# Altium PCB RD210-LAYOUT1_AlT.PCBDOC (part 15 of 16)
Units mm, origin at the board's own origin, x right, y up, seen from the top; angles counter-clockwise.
Board outline 330 x 300 mm, 6 copper layers (TOP, Mid-Layer 1, Mid-Layer 2, Mid-Layer 3, Mid-Layer 4, BOTTOM), stack 1.422 mm thick; 981 components, 463 nets, 2326 pads, 12534 vias.
Unrouted connection lines stored in the file: 6.
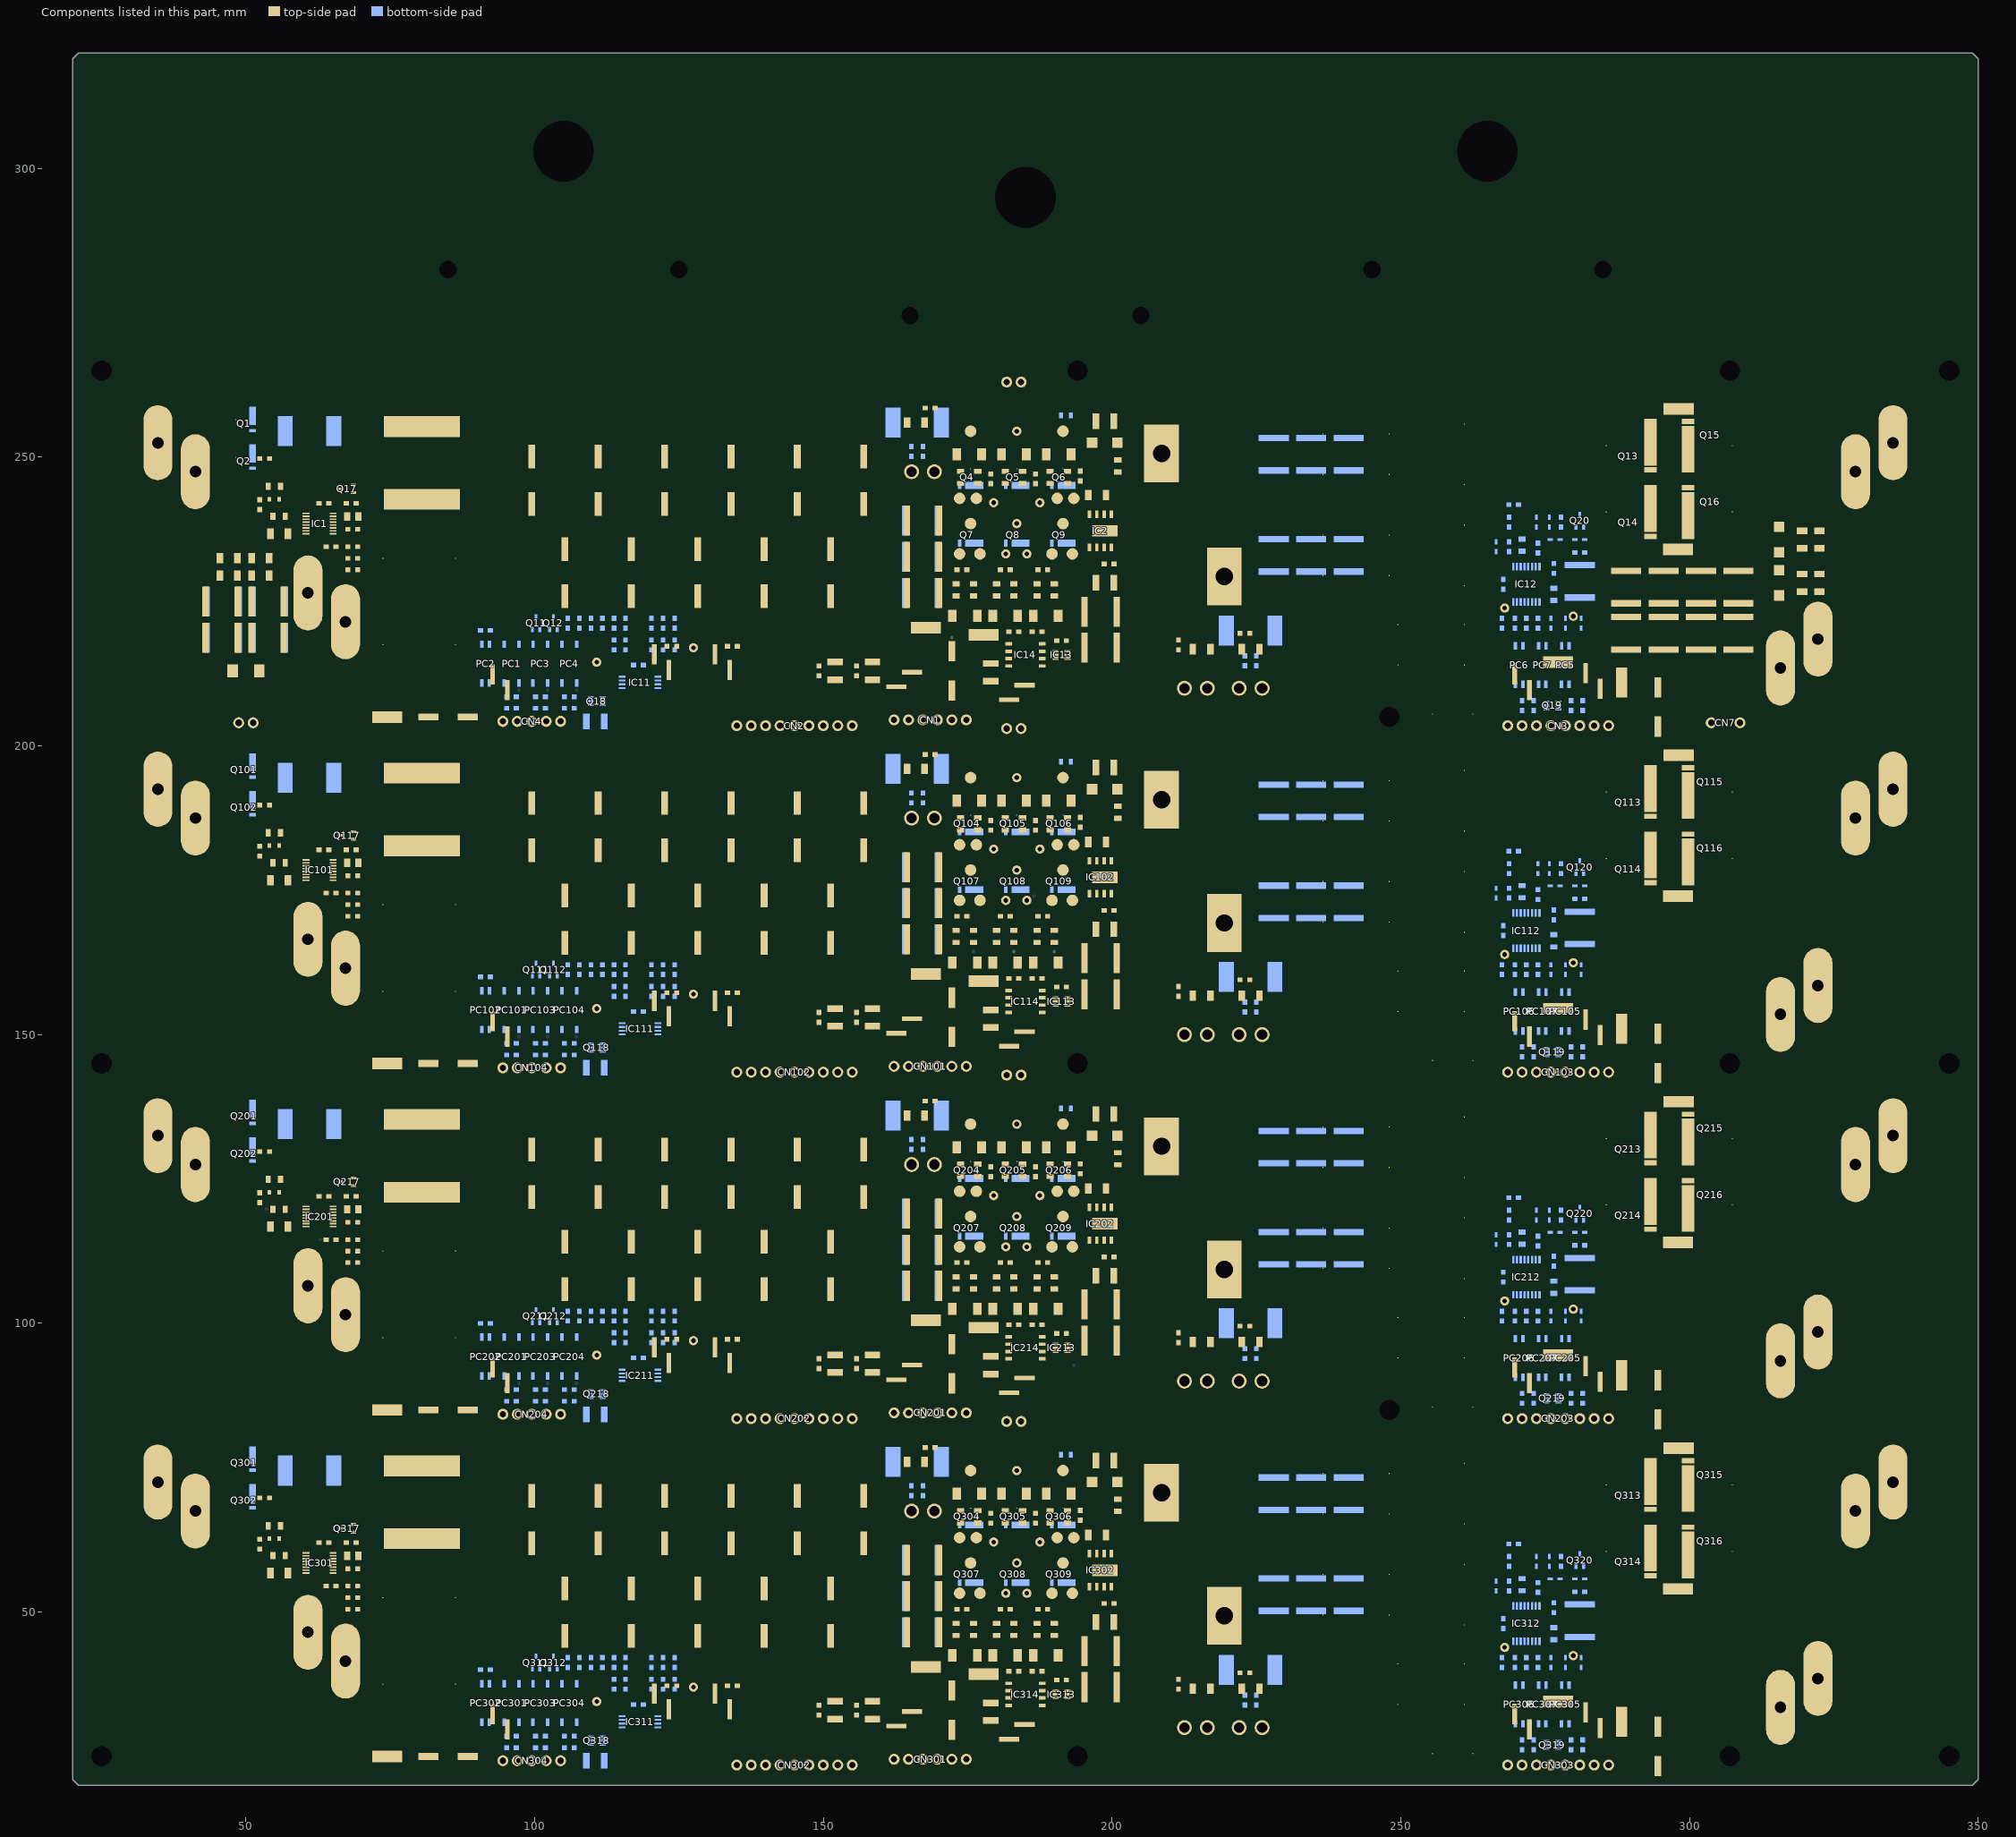
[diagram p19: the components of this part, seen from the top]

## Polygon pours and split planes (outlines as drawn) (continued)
no net on Bottom Paste "BOTTOMPASTE1205" (solid, pour order 0): 50.55,258.105 50.55,258.705 51.75,258.705 51.75,258.105
no net on Bottom Paste "BOTTOMPASTE1206" (solid, pour order 0): 44.75,254.295 44.75,254.895 45.95,254.895 45.95,254.295
no net on Bottom Paste "BOTTOMPASTE1207" (solid, pour order 0): 44.75,255.565 44.75,256.165 45.95,256.165 45.95,255.565
no net on Bottom Paste "BOTTOMPASTE1208" (solid, pour order 0): 44.75,256.835 44.75,257.435 45.95,257.435 45.95,256.835
no net on Bottom Paste "BOTTOMPASTE1209" (solid, pour order 0): 44.75,258.105 44.75,258.705 45.95,258.705 45.95,258.105
no net on Bottom Paste "BOTTOMPASTE1210" (solid, pour order 0): 48,256.7 48,258.355 49.2,258.355 49.2,256.7
no net on Bottom Paste "BOTTOMPASTE1211" (solid, pour order 0): 46.4,256.7 46.4,258.355 47.6,258.355 47.6,256.7
no net on Bottom Paste "BOTTOMPASTE1212" (solid, pour order 0): 46.4,254.645 46.4,256.3 47.6,256.3 47.6,254.645
no net on Bottom Paste "BOTTOMPASTE1213" (solid, pour order 0): 48,254.645 48,256.3 49.2,256.3 49.2,254.645
no net on Bottom Paste "BOTTOMPASTE1214" (solid, pour order 0): 50.55,249.065 50.55,249.665 51.75,249.665 51.75,249.065
no net on Bottom Paste "BOTTOMPASTE1215" (solid, pour order 0): 50.55,251.605 50.55,252.205 51.75,252.205 51.75,251.605
no net on Bottom Paste "BOTTOMPASTE1216" (solid, pour order 0): 44.75,247.795 44.75,248.395 45.95,248.395 45.95,247.795
no net on Bottom Paste "BOTTOMPASTE1217" (solid, pour order 0): 44.75,249.065 44.75,249.665 45.95,249.665 45.95,249.065
no net on Bottom Paste "BOTTOMPASTE1218" (solid, pour order 0): 44.75,250.335 44.75,250.935 45.95,250.935 45.95,250.335
no net on Bottom Paste "BOTTOMPASTE1219" (solid, pour order 0): 44.75,251.605 44.75,252.205 45.95,252.205 45.95,251.605
no net on Bottom Paste "BOTTOMPASTE1220" (solid, pour order 0): 48,250.2 48,251.855 49.2,251.855 49.2,250.2
no net on Bottom Paste "BOTTOMPASTE1221" (solid, pour order 0): 46.4,250.2 46.4,251.855 47.6,251.855 47.6,250.2
no net on Bottom Paste "BOTTOMPASTE1222" (solid, pour order 0): 46.4,248.145 46.4,249.8 47.6,249.8 47.6,248.145
no net on Bottom Paste "BOTTOMPASTE1223" (solid, pour order 0): 48,248.145 48,249.8 49.2,249.8 49.2,248.145
no net on Bottom Paste "BOTTOMPASTE1224" (solid, pour order 0): 50.55,195.565 50.55,196.165 51.75,196.165 51.75,195.565
no net on Bottom Paste "BOTTOMPASTE1225" (solid, pour order 0): 50.55,198.105 50.55,198.705 51.75,198.705 51.75,198.105
no net on Bottom Paste "BOTTOMPASTE1226" (solid, pour order 0): 44.75,194.295 44.75,194.895 45.95,194.895 45.95,194.295
no net on Bottom Paste "BOTTOMPASTE1227" (solid, pour order 0): 44.75,195.565 44.75,196.165 45.95,196.165 45.95,195.565
no net on Bottom Paste "BOTTOMPASTE1228" (solid, pour order 0): 44.75,196.835 44.75,197.435 45.95,197.435 45.95,196.835
no net on Bottom Paste "BOTTOMPASTE1229" (solid, pour order 0): 44.75,198.105 44.75,198.705 45.95,198.705 45.95,198.105
no net on Bottom Paste "BOTTOMPASTE1230" (solid, pour order 0): 48,196.7 48,198.355 49.2,198.355 49.2,196.7
no net on Bottom Paste "BOTTOMPASTE1231" (solid, pour order 0): 46.4,196.7 46.4,198.355 47.6,198.355 47.6,196.7
no net on Bottom Paste "BOTTOMPASTE1232" (solid, pour order 0): 46.4,194.645 46.4,196.3 47.6,196.3 47.6,194.645
no net on Bottom Paste "BOTTOMPASTE1233" (solid, pour order 0): 48,194.645 48,196.3 49.2,196.3 49.2,194.645
no net on Bottom Paste "BOTTOMPASTE1234" (solid, pour order 0): 50.55,189.065 50.55,189.665 51.75,189.665 51.75,189.065
no net on Bottom Paste "BOTTOMPASTE1235" (solid, pour order 0): 50.55,191.605 50.55,192.205 51.75,192.205 51.75,191.605
no net on Bottom Paste "BOTTOMPASTE1236" (solid, pour order 0): 44.75,187.795 44.75,188.395 45.95,188.395 45.95,187.795
no net on Bottom Paste "BOTTOMPASTE1237" (solid, pour order 0): 44.75,189.065 44.75,189.665 45.95,189.665 45.95,189.065
no net on Bottom Paste "BOTTOMPASTE1238" (solid, pour order 0): 44.75,190.335 44.75,190.935 45.95,190.935 45.95,190.335
no net on Bottom Paste "BOTTOMPASTE1239" (solid, pour order 0): 44.75,191.605 44.75,192.205 45.95,192.205 45.95,191.605
no net on Bottom Paste "BOTTOMPASTE1240" (solid, pour order 0): 48,190.2 48,191.855 49.2,191.855 49.2,190.2
no net on Bottom Paste "BOTTOMPASTE1241" (solid, pour order 0): 46.4,190.2 46.4,191.855 47.6,191.855 47.6,190.2
no net on Bottom Paste "BOTTOMPASTE1242" (solid, pour order 0): 46.4,188.145 46.4,189.8 47.6,189.8 47.6,188.145
no net on Bottom Paste "BOTTOMPASTE1243" (solid, pour order 0): 48,188.145 48,189.8 49.2,189.8 49.2,188.145
no net on Bottom Paste "BOTTOMPASTE1244" (solid, pour order 0): 174.565,184.5 174.565,185.7 175.165,185.7 175.165,184.5
no net on Bottom Paste "BOTTOMPASTE1245" (solid, pour order 0): 177.105,184.5 177.105,185.7 177.705,185.7 177.705,184.5
no net on Bottom Paste "BOTTOMPASTE1246" (solid, pour order 0): 173.295,190.3 173.295,191.5 173.895,191.5 173.895,190.3
no net on Bottom Paste "BOTTOMPASTE1247" (solid, pour order 0): 174.565,190.3 174.565,191.5 175.165,191.5 175.165,190.3
no net on Bottom Paste "BOTTOMPASTE1248" (solid, pour order 0): 175.835,190.3 175.835,191.5 176.435,191.5 176.435,190.3
no net on Bottom Paste "BOTTOMPASTE1249" (solid, pour order 0): 177.105,190.3 177.105,191.5 177.705,191.5 177.705,190.3
no net on Bottom Paste "BOTTOMPASTE1250" (solid, pour order 0): 175.7,187.05 175.7,188.25 177.355,188.25 177.355,187.05
no net on Bottom Paste "BOTTOMPASTE1251" (solid, pour order 0): 175.7,188.65 175.7,189.85 177.355,189.85 177.355,188.65
no net on Bottom Paste "BOTTOMPASTE1252" (solid, pour order 0): 173.645,188.65 173.645,189.85 175.3,189.85 175.3,188.65
no net on Bottom Paste "BOTTOMPASTE1253" (solid, pour order 0): 173.645,187.05 173.645,188.25 175.3,188.25 175.3,187.05
no net on Bottom Paste "BOTTOMPASTE1254" (solid, pour order 0): 182.565,184.5 182.565,185.7 183.165,185.7 183.165,184.5
no net on Bottom Paste "BOTTOMPASTE1255" (solid, pour order 0): 185.105,184.5 185.105,185.7 185.705,185.7 185.705,184.5
no net on Bottom Paste "BOTTOMPASTE1256" (solid, pour order 0): 181.295,190.3 181.295,191.5 181.895,191.5 181.895,190.3
no net on Bottom Paste "BOTTOMPASTE1257" (solid, pour order 0): 182.565,190.3 182.565,191.5 183.165,191.5 183.165,190.3
no net on Bottom Paste "BOTTOMPASTE1258" (solid, pour order 0): 183.835,190.3 183.835,191.5 184.435,191.5 184.435,190.3
no net on Bottom Paste "BOTTOMPASTE1259" (solid, pour order 0): 185.105,190.3 185.105,191.5 185.705,191.5 185.705,190.3
no net on Bottom Paste "BOTTOMPASTE1260" (solid, pour order 0): 183.7,187.05 183.7,188.25 185.355,188.25 185.355,187.05
no net on Bottom Paste "BOTTOMPASTE1261" (solid, pour order 0): 183.7,188.65 183.7,189.85 185.355,189.85 185.355,188.65
no net on Bottom Paste "BOTTOMPASTE1262" (solid, pour order 0): 181.645,188.65 181.645,189.85 183.3,189.85 183.3,188.65
no net on Bottom Paste "BOTTOMPASTE1263" (solid, pour order 0): 181.645,187.05 181.645,188.25 183.3,188.25 183.3,187.05
no net on Bottom Paste "BOTTOMPASTE1264" (solid, pour order 0): 190.565,184.5 190.565,185.7 191.165,185.7 191.165,184.5
no net on Bottom Paste "BOTTOMPASTE1265" (solid, pour order 0): 193.105,184.5 193.105,185.7 193.705,185.7 193.705,184.5
no net on Bottom Paste "BOTTOMPASTE1266" (solid, pour order 0): 189.295,190.3 189.295,191.5 189.895,191.5 189.895,190.3
no net on Bottom Paste "BOTTOMPASTE1267" (solid, pour order 0): 190.565,190.3 190.565,191.5 191.165,191.5 191.165,190.3
no net on Bottom Paste "BOTTOMPASTE1268" (solid, pour order 0): 191.835,190.3 191.835,191.5 192.435,191.5 192.435,190.3
no net on Bottom Paste "BOTTOMPASTE1269" (solid, pour order 0): 193.105,190.3 193.105,191.5 193.705,191.5 193.705,190.3
no net on Bottom Paste "BOTTOMPASTE1270" (solid, pour order 0): 191.7,187.05 191.7,188.25 193.355,188.25 193.355,187.05
no net on Bottom Paste "BOTTOMPASTE1271" (solid, pour order 0): 191.7,188.65 191.7,189.85 193.355,189.85 193.355,188.65
no net on Bottom Paste "BOTTOMPASTE1272" (solid, pour order 0): 189.645,188.65 189.645,189.85 191.3,189.85 191.3,188.65
no net on Bottom Paste "BOTTOMPASTE1273" (solid, pour order 0): 189.645,187.05 189.645,188.25 191.3,188.25 191.3,187.05
no net on Bottom Paste "BOTTOMPASTE1274" (solid, pour order 0): 174.565,174.5 174.565,175.7 175.165,175.7 175.165,174.5
no net on Bottom Paste "BOTTOMPASTE1275" (solid, pour order 0): 177.105,174.5 177.105,175.7 177.705,175.7 177.705,174.5
no net on Bottom Paste "BOTTOMPASTE1276" (solid, pour order 0): 173.295,180.3 173.295,181.5 173.895,181.5 173.895,180.3
no net on Bottom Paste "BOTTOMPASTE1277" (solid, pour order 0): 174.565,180.3 174.565,181.5 175.165,181.5 175.165,180.3
no net on Bottom Paste "BOTTOMPASTE1278" (solid, pour order 0): 175.835,180.3 175.835,181.5 176.435,181.5 176.435,180.3
no net on Bottom Paste "BOTTOMPASTE1279" (solid, pour order 0): 177.105,180.3 177.105,181.5 177.705,181.5 177.705,180.3
no net on Bottom Paste "BOTTOMPASTE1280" (solid, pour order 0): 175.7,177.05 175.7,178.25 177.355,178.25 177.355,177.05
no net on Bottom Paste "BOTTOMPASTE1281" (solid, pour order 0): 175.7,178.65 175.7,179.85 177.355,179.85 177.355,178.65
no net on Bottom Paste "BOTTOMPASTE1282" (solid, pour order 0): 173.645,178.65 173.645,179.85 175.3,179.85 175.3,178.65
no net on Bottom Paste "BOTTOMPASTE1283" (solid, pour order 0): 173.645,177.05 173.645,178.25 175.3,178.25 175.3,177.05
no net on Bottom Paste "BOTTOMPASTE1284" (solid, pour order 0): 182.565,174.5 182.565,175.7 183.165,175.7 183.165,174.5
no net on Bottom Paste "BOTTOMPASTE1285" (solid, pour order 0): 185.105,174.5 185.105,175.7 185.705,175.7 185.705,174.5
no net on Bottom Paste "BOTTOMPASTE1286" (solid, pour order 0): 181.295,180.3 181.295,181.5 181.895,181.5 181.895,180.3
no net on Bottom Paste "BOTTOMPASTE1287" (solid, pour order 0): 182.565,180.3 182.565,181.5 183.165,181.5 183.165,180.3
no net on Bottom Paste "BOTTOMPASTE1288" (solid, pour order 0): 183.835,180.3 183.835,181.5 184.435,181.5 184.435,180.3
no net on Bottom Paste "BOTTOMPASTE1289" (solid, pour order 0): 185.105,180.3 185.105,181.5 185.705,181.5 185.705,180.3
no net on Bottom Paste "BOTTOMPASTE1290" (solid, pour order 0): 183.7,177.05 183.7,178.25 185.355,178.25 185.355,177.05
no net on Bottom Paste "BOTTOMPASTE1291" (solid, pour order 0): 183.7,178.65 183.7,179.85 185.355,179.85 185.355,178.65
no net on Bottom Paste "BOTTOMPASTE1292" (solid, pour order 0): 181.645,178.65 181.645,179.85 183.3,179.85 183.3,178.65
no net on Bottom Paste "BOTTOMPASTE1293" (solid, pour order 0): 181.645,177.05 181.645,178.25 183.3,178.25 183.3,177.05
no net on Bottom Paste "BOTTOMPASTE1294" (solid, pour order 0): 190.565,174.5 190.565,175.7 191.165,175.7 191.165,174.5
no net on Bottom Paste "BOTTOMPASTE1295" (solid, pour order 0): 193.105,174.5 193.105,175.7 193.705,175.7 193.705,174.5
no net on Bottom Paste "BOTTOMPASTE1296" (solid, pour order 0): 189.295,180.3 189.295,181.5 189.895,181.5 189.895,180.3
no net on Bottom Paste "BOTTOMPASTE1297" (solid, pour order 0): 190.565,180.3 190.565,181.5 191.165,181.5 191.165,180.3
no net on Bottom Paste "BOTTOMPASTE1298" (solid, pour order 0): 191.835,180.3 191.835,181.5 192.435,181.5 192.435,180.3
no net on Bottom Paste "BOTTOMPASTE1299" (solid, pour order 0): 193.105,180.3 193.105,181.5 193.705,181.5 193.705,180.3
no net on Bottom Paste "BOTTOMPASTE1300" (solid, pour order 0): 191.7,177.05 191.7,178.25 193.355,178.25 193.355,177.05
no net on Bottom Paste "BOTTOMPASTE1301" (solid, pour order 0): 191.7,178.65 191.7,179.85 193.355,179.85 193.355,178.65
no net on Bottom Paste "BOTTOMPASTE1302" (solid, pour order 0): 189.645,178.65 189.645,179.85 191.3,179.85 191.3,178.65
no net on Bottom Paste "BOTTOMPASTE1303" (solid, pour order 0): 189.645,177.05 189.645,178.25 191.3,178.25 191.3,177.05
no net on Top Solder "TOPSOLDER1304" (solid, pour order 0): 292.1,248.5 292.1,249.5 294.4,249.5 294.4,248.5
no net on Top Solder "TOPSOLDER1305" (solid, pour order 0): 292.1,249.7 292.1,250.7 294.4,250.7 294.4,249.7
no net on Top Solder "TOPSOLDER1306" (solid, pour order 0): 292.1,250.9 292.1,251.9 294.4,251.9 294.4,250.9
no net on Top Solder "TOPSOLDER1307" (solid, pour order 0): 292.1,253.3 292.1,254.3 294.4,254.3 294.4,253.3
no net on Top Solder "TOPSOLDER1308" (solid, pour order 0): 292.1,254.5 292.1,255.5 294.4,255.5 294.4,254.5
no net on Top Solder "TOPSOLDER1309" (solid, pour order 0): 292.1,255.7 292.1,256.7 294.4,256.7 294.4,255.7
no net on Top Solder "TOPSOLDER1310" (solid, pour order 0): 292.1,237 292.1,238 294.4,238 294.4,237
no net on Top Solder "TOPSOLDER1311" (solid, pour order 0): 292.1,238.2 292.1,239.2 294.4,239.2 294.4,238.2
no net on Top Solder "TOPSOLDER1312" (solid, pour order 0): 292.1,239.4 292.1,240.4 294.4,240.4 294.4,239.4
no net on Top Solder "TOPSOLDER1313" (solid, pour order 0): 292.1,241.8 292.1,242.8 294.4,242.8 294.4,241.8
no net on Top Solder "TOPSOLDER1314" (solid, pour order 0): 292.1,243 292.1,244 294.4,244 294.4,243
no net on Top Solder "TOPSOLDER1315" (solid, pour order 0): 292.1,244.2 292.1,245.2 294.4,245.2 294.4,244.2
no net on Top Solder "TOPSOLDER1316" (solid, pour order 0): 298.6,254.5 298.6,255.5 300.9,255.5 300.9,254.5
no net on Top Solder "TOPSOLDER1317" (solid, pour order 0): 298.6,253.3 298.6,254.3 300.9,254.3 300.9,253.3
no net on Top Solder "TOPSOLDER1318" (solid, pour order 0): 298.6,252.1 298.6,253.1 300.9,253.1 300.9,252.1
no net on Top Solder "TOPSOLDER1319" (solid, pour order 0): 298.6,249.7 298.6,250.7 300.9,250.7 300.9,249.7
no net on Top Solder "TOPSOLDER1320" (solid, pour order 0): 298.6,248.5 298.6,249.5 300.9,249.5 300.9,248.5
no net on Top Solder "TOPSOLDER1321" (solid, pour order 0): 298.6,247.3 298.6,248.3 300.9,248.3 300.9,247.3
no net on Top Solder "TOPSOLDER1322" (solid, pour order 0): 298.6,243 298.6,244 300.9,244 300.9,243
no net on Top Solder "TOPSOLDER1323" (solid, pour order 0): 298.6,241.8 298.6,242.8 300.9,242.8 300.9,241.8
no net on Top Solder "TOPSOLDER1324" (solid, pour order 0): 298.6,240.6 298.6,241.6 300.9,241.6 300.9,240.6
no net on Top Solder "TOPSOLDER1325" (solid, pour order 0): 298.6,238.2 298.6,239.2 300.9,239.2 300.9,238.2
no net on Top Solder "TOPSOLDER1326" (solid, pour order 0): 298.6,237 298.6,238 300.9,238 300.9,237
no net on Top Solder "TOPSOLDER1327" (solid, pour order 0): 298.6,235.8 298.6,236.8 300.9,236.8 300.9,235.8
no net on Top Solder "TOPSOLDER1328" (solid, pour order 0): 292.1,177 292.1,178 294.4,178 294.4,177
no net on Top Solder "TOPSOLDER1329" (solid, pour order 0): 292.1,178.2 292.1,179.2 294.4,179.2 294.4,178.2
no net on Top Solder "TOPSOLDER1330" (solid, pour order 0): 292.1,179.4 292.1,180.4 294.4,180.4 294.4,179.4
no net on Top Solder "TOPSOLDER1331" (solid, pour order 0): 292.1,181.8 292.1,182.8 294.4,182.8 294.4,181.8
no net on Top Solder "TOPSOLDER1332" (solid, pour order 0): 292.1,183 292.1,184 294.4,184 294.4,183
no net on Top Solder "TOPSOLDER1333" (solid, pour order 0): 292.1,184.2 292.1,185.2 294.4,185.2 294.4,184.2
no net on Top Solder "TOPSOLDER1334" (solid, pour order 0): 292.1,188.5 292.1,189.5 294.4,189.5 294.4,188.5
no net on Top Solder "TOPSOLDER1335" (solid, pour order 0): 292.1,189.7 292.1,190.7 294.4,190.7 294.4,189.7
no net on Top Solder "TOPSOLDER1336" (solid, pour order 0): 292.1,190.9 292.1,191.9 294.4,191.9 294.4,190.9
no net on Top Solder "TOPSOLDER1337" (solid, pour order 0): 292.1,193.3 292.1,194.3 294.4,194.3 294.4,193.3
no net on Top Solder "TOPSOLDER1338" (solid, pour order 0): 292.1,194.5 292.1,195.5 294.4,195.5 294.4,194.5
no net on Top Solder "TOPSOLDER1339" (solid, pour order 0): 292.1,195.7 292.1,196.7 294.4,196.7 294.4,195.7
no net on Top Solder "TOPSOLDER1340" (solid, pour order 0): 298.6,183 298.6,184 300.9,184 300.9,183
no net on Top Solder "TOPSOLDER1341" (solid, pour order 0): 298.6,181.8 298.6,182.8 300.9,182.8 300.9,181.8
no net on Top Solder "TOPSOLDER1342" (solid, pour order 0): 298.6,180.6 298.6,181.6 300.9,181.6 300.9,180.6
no net on Top Solder "TOPSOLDER1343" (solid, pour order 0): 298.6,178.2 298.6,179.2 300.9,179.2 300.9,178.2
no net on Top Solder "TOPSOLDER1344" (solid, pour order 0): 298.6,177 298.6,178 300.9,178 300.9,177
no net on Top Solder "TOPSOLDER1345" (solid, pour order 0): 298.6,175.8 298.6,176.8 300.9,176.8 300.9,175.8
no net on Top Solder "TOPSOLDER1346" (solid, pour order 0): 298.6,194.5 298.6,195.5 300.9,195.5 300.9,194.5
no net on Top Solder "TOPSOLDER1347" (solid, pour order 0): 298.6,193.3 298.6,194.3 300.9,194.3 300.9,193.3
no net on Top Solder "TOPSOLDER1348" (solid, pour order 0): 298.6,192.1 298.6,193.1 300.9,193.1 300.9,192.1
no net on Top Solder "TOPSOLDER1349" (solid, pour order 0): 298.6,189.7 298.6,190.7 300.9,190.7 300.9,189.7
no net on Top Solder "TOPSOLDER1350" (solid, pour order 0): 298.6,188.5 298.6,189.5 300.9,189.5 300.9,188.5
no net on Top Solder "TOPSOLDER1351" (solid, pour order 0): 298.6,187.3 298.6,188.3 300.9,188.3 300.9,187.3
no net on Top Solder "TOPSOLDER1352" (solid, pour order 0): 292.1,117 292.1,118 294.4,118 294.4,117
no net on Top Solder "TOPSOLDER1353" (solid, pour order 0): 292.1,118.2 292.1,119.2 294.4,119.2 294.4,118.2
no net on Top Solder "TOPSOLDER1354" (solid, pour order 0): 292.1,119.4 292.1,120.4 294.4,120.4 294.4,119.4
no net on Top Solder "TOPSOLDER1355" (solid, pour order 0): 292.1,121.8 292.1,122.8 294.4,122.8 294.4,121.8
no net on Top Solder "TOPSOLDER1356" (solid, pour order 0): 292.1,123 292.1,124 294.4,124 294.4,123
no net on Top Solder "TOPSOLDER1357" (solid, pour order 0): 292.1,124.2 292.1,125.2 294.4,125.2 294.4,124.2
no net on Top Solder "TOPSOLDER1358" (solid, pour order 0): 292.1,128.5 292.1,129.5 294.4,129.5 294.4,128.5
no net on Top Solder "TOPSOLDER1359" (solid, pour order 0): 292.1,129.7 292.1,130.7 294.4,130.7 294.4,129.7
no net on Top Solder "TOPSOLDER1360" (solid, pour order 0): 292.1,130.9 292.1,131.9 294.4,131.9 294.4,130.9
no net on Top Solder "TOPSOLDER1361" (solid, pour order 0): 292.1,133.3 292.1,134.3 294.4,134.3 294.4,133.3
no net on Top Solder "TOPSOLDER1362" (solid, pour order 0): 292.1,134.5 292.1,135.5 294.4,135.5 294.4,134.5
no net on Top Solder "TOPSOLDER1363" (solid, pour order 0): 292.1,135.7 292.1,136.7 294.4,136.7 294.4,135.7
no net on Top Solder "TOPSOLDER1364" (solid, pour order 0): 298.6,123 298.6,124 300.9,124 300.9,123
no net on Top Solder "TOPSOLDER1365" (solid, pour order 0): 298.6,121.8 298.6,122.8 300.9,122.8 300.9,121.8
no net on Top Solder "TOPSOLDER1366" (solid, pour order 0): 298.6,120.6 298.6,121.6 300.9,121.6 300.9,120.6
no net on Top Solder "TOPSOLDER1367" (solid, pour order 0): 298.6,118.2 298.6,119.2 300.9,119.2 300.9,118.2
no net on Top Solder "TOPSOLDER1368" (solid, pour order 0): 298.6,117 298.6,118 300.9,118 300.9,117
no net on Top Solder "TOPSOLDER1369" (solid, pour order 0): 298.6,115.8 298.6,116.8 300.9,116.8 300.9,115.8
no net on Top Solder "TOPSOLDER1370" (solid, pour order 0): 298.6,134.5 298.6,135.5 300.9,135.5 300.9,134.5
no net on Top Solder "TOPSOLDER1371" (solid, pour order 0): 298.6,133.3 298.6,134.3 300.9,134.3 300.9,133.3
no net on Top Solder "TOPSOLDER1372" (solid, pour order 0): 298.6,132.1 298.6,133.1 300.9,133.1 300.9,132.1
no net on Top Solder "TOPSOLDER1373" (solid, pour order 0): 298.6,129.7 298.6,130.7 300.9,130.7 300.9,129.7
no net on Top Solder "TOPSOLDER1374" (solid, pour order 0): 298.6,128.5 298.6,129.5 300.9,129.5 300.9,128.5
no net on Top Solder "TOPSOLDER1375" (solid, pour order 0): 298.6,127.3 298.6,128.3 300.9,128.3 300.9,127.3
no net on Top Solder "TOPSOLDER1376" (solid, pour order 0): 292.1,57 292.1,58 294.4,58 294.4,57
no net on Top Solder "TOPSOLDER1377" (solid, pour order 0): 292.1,58.2 292.1,59.2 294.4,59.2 294.4,58.2
no net on Top Solder "TOPSOLDER1378" (solid, pour order 0): 292.1,59.4 292.1,60.4 294.4,60.4 294.4,59.4
no net on Top Solder "TOPSOLDER1379" (solid, pour order 0): 292.1,61.8 292.1,62.8 294.4,62.8 294.4,61.8
no net on Top Solder "TOPSOLDER1380" (solid, pour order 0): 292.1,63 292.1,64 294.4,64 294.4,63
no net on Top Solder "TOPSOLDER1381" (solid, pour order 0): 292.1,64.2 292.1,65.2 294.4,65.2 294.4,64.2
no net on Top Solder "TOPSOLDER1382" (solid, pour order 0): 292.1,68.5 292.1,69.5 294.4,69.5 294.4,68.5
no net on Top Solder "TOPSOLDER1383" (solid, pour order 0): 292.1,69.7 292.1,70.7 294.4,70.7 294.4,69.7
no net on Top Solder "TOPSOLDER1384" (solid, pour order 0): 292.1,70.9 292.1,71.9 294.4,71.9 294.4,70.9
no net on Top Solder "TOPSOLDER1385" (solid, pour order 0): 292.1,73.3 292.1,74.3 294.4,74.3 294.4,73.3
no net on Top Solder "TOPSOLDER1386" (solid, pour order 0): 292.1,74.5 292.1,75.5 294.4,75.5 294.4,74.5
no net on Top Solder "TOPSOLDER1387" (solid, pour order 0): 292.1,75.7 292.1,76.7 294.4,76.7 294.4,75.7
no net on Top Solder "TOPSOLDER1388" (solid, pour order 0): 298.6,63 298.6,64 300.9,64 300.9,63
no net on Top Solder "TOPSOLDER1389" (solid, pour order 0): 298.6,61.8 298.6,62.8 300.9,62.8 300.9,61.8
no net on Top Solder "TOPSOLDER1390" (solid, pour order 0): 298.6,60.6 298.6,61.6 300.9,61.6 300.9,60.6
no net on Top Solder "TOPSOLDER1391" (solid, pour order 0): 298.6,58.2 298.6,59.2 300.9,59.2 300.9,58.2
no net on Top Solder "TOPSOLDER1392" (solid, pour order 0): 298.6,57 298.6,58 300.9,58 300.9,57
no net on Top Solder "TOPSOLDER1393" (solid, pour order 0): 298.6,55.8 298.6,56.8 300.9,56.8 300.9,55.8
no net on Top Solder "TOPSOLDER1394" (solid, pour order 0): 298.6,74.5 298.6,75.5 300.9,75.5 300.9,74.5
no net on Top Solder "TOPSOLDER1395" (solid, pour order 0): 298.6,73.3 298.6,74.3 300.9,74.3 300.9,73.3
no net on Top Solder "TOPSOLDER1396" (solid, pour order 0): 298.6,72.1 298.6,73.1 300.9,73.1 300.9,72.1
no net on Top Solder "TOPSOLDER1397" (solid, pour order 0): 298.6,69.7 298.6,70.7 300.9,70.7 300.9,69.7
no net on Top Solder "TOPSOLDER1398" (solid, pour order 0): 298.6,68.5 298.6,69.5 300.9,69.5 300.9,68.5
no net on Top Solder "TOPSOLDER1399" (solid, pour order 0): 298.6,67.3 298.6,68.3 300.9,68.3 300.9,67.3
no net on Top Solder "TOPSOLDER1400" (solid, pour order 0): 35 vertices, not listed, extent 214.5,213 281,259
no net on Top Solder "TOPSOLDER1401" (solid, pour order 0): 254,226.25 251.25,229 231.35,229 231.35,254.25 252.2,254.25 255.25,257.3 266.8,257.3 267.8,256.3 267.8,229.529 ccw(c268.75,228) 266.95,228 266.95,226.25
no net on Top Solder "TOPSOLDER1402" (solid, pour order 0): 244.375,218.5 244.375,221.5 269.25,221.5 269.25,218.5 262.02,218.5 ccw(c261,218.75) 259.98,218.5
no net on Top Solder "TOPSOLDER1403" (solid, pour order 0): 255.15,166.25 253.525,167.875 232.325,167.875 231.35,168.85 231.35,194.65 232.35,195.65 253.55,195.65 255.2,197.3 266.8,197.3 267.8,196.3 267.8,169.529 ccw(c268.75,168) 266.95,168 266.95,166.25
no net on Top Solder "TOPSOLDER1404" (solid, pour order 0): 244.35,158.5 244.35,161.65 245.35,162.65 269.25,162.65 269.25,158.5 262.02,158.5 ccw(c261,158.75) 259.98,158.5
no net on Top Solder "TOPSOLDER1405" (solid, pour order 0): 255.15,106.25 253.525,107.875 232.325,107.875 231.35,108.85 231.35,134.65 232.35,135.65 253.55,135.65 255.2,137.3 266.8,137.3 267.8,136.3 267.8,109.529 ccw(c268.75,108) 266.95,108 266.95,106.25
no net on Top Solder "TOPSOLDER1406" (solid, pour order 0): 244.35,98.5 244.35,101.65 245.35,102.65 269.25,102.65 269.25,98.5 262.02,98.5 ccw(c261,98.75) 259.98,98.5
no net on Top Solder "TOPSOLDER1407" (solid, pour order 0): 255.15,46.25 253.525,47.875 232.325,47.875 231.35,48.85 231.35,74.65 232.35,75.65 253.55,75.65 255.2,77.3 266.8,77.3 267.8,76.3 267.8,49.529 ccw(c268.75,48) 266.95,48 266.95,46.25
no net on Top Solder "TOPSOLDER1408" (solid, pour order 0): 244.35,38.5 244.35,41.65 245.35,42.65 269.25,42.65 269.25,38.5 262.02,38.5 ccw(c261,38.75) 259.98,38.5
no net on Top Solder "TOPSOLDER1409" (solid, pour order 0): 34 vertices, not listed, extent 214.5,154.875 281,199
no net on Top Solder "TOPSOLDER1410" (solid, pour order 0): 35 vertices, not listed, extent 214.5,94.875 281,139
no net on Top Solder "TOPSOLDER1411" (solid, pour order 0): 35 vertices, not listed, extent 214.5,34.875 281,79
no net on Top Solder "TOPSOLDER1412" (solid, pour order 0): 99.25,303 ccw(c105,303) 110.75,303 ccw(c105,303)
no net on Top Solder "TOPSOLDER1413" (solid, pour order 0): 179.25,295 ccw(c185,295) 190.75,295 ccw(c185,295)
no net on Top Solder "TOPSOLDER1414" (solid, pour order 0): 259.25,303 ccw(c265,303) 270.75,303 ccw(c265,303)
no net on Top Solder "TOPSOLDER1415" (solid, pour order 0): 80.5,280.5 80.5,284.5 89.5,284.5 89.5,280.5
no net on Top Solder "TOPSOLDER1416" (solid, pour order 0): 120.5,280.5 120.5,284.5 129.5,284.5 129.5,280.5
no net on Top Solder "TOPSOLDER1417" (solid, pour order 0): 160.5,272.5 160.5,276.5 169.5,276.5 169.5,272.5
no net on Top Solder "TOPSOLDER1418" (solid, pour order 0): 200.5,272.5 200.5,276.5 209.5,276.5 209.5,272.5
no net on Top Solder "TOPSOLDER1419" (solid, pour order 0): 240.5,280.5 240.5,284.5 249.5,284.5 249.5,280.5
no net on Top Solder "TOPSOLDER1420" (solid, pour order 0): 280.5,280.5 280.5,284.5 289.5,284.5 289.5,280.5
no net on Bottom Solder "BOTTOMSOLDER1421" (solid, pour order 0): 177.055,244.45 177.055,245.75 177.755,245.75 177.755,244.45
no net on Bottom Solder "BOTTOMSOLDER1422" (solid, pour order 0): 174.515,244.45 174.515,245.75 175.215,245.75 175.215,244.45
no net on Bottom Solder "BOTTOMSOLDER1423" (solid, pour order 0): 173.245,250.25 173.245,251.55 173.945,251.55 173.945,250.25
no net on Bottom Solder "BOTTOMSOLDER1424" (solid, pour order 0): 174.515,250.25 174.515,251.55 175.215,251.55 175.215,250.25
no net on Bottom Solder "BOTTOMSOLDER1425" (solid, pour order 0): 175.785,250.25 175.785,251.55 176.485,251.55 176.485,250.25
no net on Bottom Solder "BOTTOMSOLDER1426" (solid, pour order 0): 177.055,250.25 177.055,251.55 177.755,251.55 177.755,250.25
no net on Bottom Solder "BOTTOMSOLDER1427" (solid, pour order 0): 21 vertices, not listed, extent 172.7,246.65 178.3,249.95
no net on Bottom Solder "BOTTOMSOLDER1428" (solid, pour order 0): 177.055,234.45 177.055,235.75 177.755,235.75 177.755,234.45
no net on Bottom Solder "BOTTOMSOLDER1429" (solid, pour order 0): 174.515,234.45 174.515,235.75 175.215,235.75 175.215,234.45
no net on Bottom Solder "BOTTOMSOLDER1430" (solid, pour order 0): 173.245,240.25 173.245,241.55 173.945,241.55 173.945,240.25
no net on Bottom Solder "BOTTOMSOLDER1431" (solid, pour order 0): 174.515,240.25 174.515,241.55 175.215,241.55 175.215,240.25
no net on Bottom Solder "BOTTOMSOLDER1432" (solid, pour order 0): 175.785,240.25 175.785,241.55 176.485,241.55 176.485,240.25
no net on Bottom Solder "BOTTOMSOLDER1433" (solid, pour order 0): 177.055,240.25 177.055,241.55 177.755,241.55 177.755,240.25
no net on Bottom Solder "BOTTOMSOLDER1434" (solid, pour order 0): 21 vertices, not listed, extent 172.7,236.65 178.3,239.95
no net on Bottom Solder "BOTTOMSOLDER1435" (solid, pour order 0): 185.055,244.45 185.055,245.75 185.755,245.75 185.755,244.45
no net on Bottom Solder "BOTTOMSOLDER1436" (solid, pour order 0): 182.515,244.45 182.515,245.75 183.215,245.75 183.215,244.45
no net on Bottom Solder "BOTTOMSOLDER1437" (solid, pour order 0): 181.245,250.25 181.245,251.55 181.945,251.55 181.945,250.25
no net on Bottom Solder "BOTTOMSOLDER1438" (solid, pour order 0): 182.515,250.25 182.515,251.55 183.215,251.55 183.215,250.25
no net on Bottom Solder "BOTTOMSOLDER1439" (solid, pour order 0): 183.785,250.25 183.785,251.55 184.485,251.55 184.485,250.25
no net on Bottom Solder "BOTTOMSOLDER1440" (solid, pour order 0): 185.055,250.25 185.055,251.55 185.755,251.55 185.755,250.25
no net on Bottom Solder "BOTTOMSOLDER1441" (solid, pour order 0): 21 vertices, not listed, extent 180.7,246.65 186.3,249.95
no net on Bottom Solder "BOTTOMSOLDER1442" (solid, pour order 0): 185.055,234.45 185.055,235.75 185.755,235.75 185.755,234.45
no net on Bottom Solder "BOTTOMSOLDER1443" (solid, pour order 0): 182.515,234.45 182.515,235.75 183.215,235.75 183.215,234.45
no net on Bottom Solder "BOTTOMSOLDER1444" (solid, pour order 0): 181.245,240.25 181.245,241.55 181.945,241.55 181.945,240.25
no net on Bottom Solder "BOTTOMSOLDER1445" (solid, pour order 0): 182.515,240.25 182.515,241.55 183.215,241.55 183.215,240.25
no net on Bottom Solder "BOTTOMSOLDER1446" (solid, pour order 0): 183.785,240.25 183.785,241.55 184.485,241.55 184.485,240.25
no net on Bottom Solder "BOTTOMSOLDER1447" (solid, pour order 0): 185.055,240.25 185.055,241.55 185.755,241.55 185.755,240.25
no net on Bottom Solder "BOTTOMSOLDER1448" (solid, pour order 0): 21 vertices, not listed, extent 180.7,236.65 186.3,239.95
no net on Bottom Solder "BOTTOMSOLDER1449" (solid, pour order 0): 193.055,244.45 193.055,245.75 193.755,245.75 193.755,244.45
no net on Bottom Solder "BOTTOMSOLDER1450" (solid, pour order 0): 190.515,244.45 190.515,245.75 191.215,245.75 191.215,244.45
no net on Bottom Solder "BOTTOMSOLDER1451" (solid, pour order 0): 189.245,250.25 189.245,251.55 189.945,251.55 189.945,250.25
no net on Bottom Solder "BOTTOMSOLDER1452" (solid, pour order 0): 190.515,250.25 190.515,251.55 191.215,251.55 191.215,250.25
no net on Bottom Solder "BOTTOMSOLDER1453" (solid, pour order 0): 191.785,250.25 191.785,251.55 192.485,251.55 192.485,250.25
no net on Bottom Solder "BOTTOMSOLDER1454" (solid, pour order 0): 193.055,250.25 193.055,251.55 193.755,251.55 193.755,250.25
no net on Bottom Solder "BOTTOMSOLDER1455" (solid, pour order 0): 21 vertices, not listed, extent 188.7,246.65 194.3,249.95
no net on Bottom Solder "BOTTOMSOLDER1456" (solid, pour order 0): 193.055,234.45 193.055,235.75 193.755,235.75 193.755,234.45
no net on Bottom Solder "BOTTOMSOLDER1457" (solid, pour order 0): 190.515,234.45 190.515,235.75 191.215,235.75 191.215,234.45
no net on Bottom Solder "BOTTOMSOLDER1458" (solid, pour order 0): 189.245,240.25 189.245,241.55 189.945,241.55 189.945,240.25
no net on Bottom Solder "BOTTOMSOLDER1459" (solid, pour order 0): 190.515,240.25 190.515,241.55 191.215,241.55 191.215,240.25
no net on Bottom Solder "BOTTOMSOLDER1460" (solid, pour order 0): 191.785,240.25 191.785,241.55 192.485,241.55 192.485,240.25
no net on Bottom Solder "BOTTOMSOLDER1461" (solid, pour order 0): 193.055,240.25 193.055,241.55 193.755,241.55 193.755,240.25
no net on Bottom Solder "BOTTOMSOLDER1462" (solid, pour order 0): 21 vertices, not listed, extent 188.7,236.65 194.3,239.95
no net on Bottom Solder "BOTTOMSOLDER1463" (solid, pour order 0): 50.5,138.055 50.5,138.755 51.8,138.755 51.8,138.055
no net on Bottom Solder "BOTTOMSOLDER1464" (solid, pour order 0): 50.5,135.515 50.5,136.215 51.8,136.215 51.8,135.515
no net on Bottom Solder "BOTTOMSOLDER1465" (solid, pour order 0): 44.7,134.245 44.7,134.945 46,134.945 46,134.245
no net on Bottom Solder "BOTTOMSOLDER1466" (solid, pour order 0): 44.7,135.515 44.7,136.215 46,136.215 46,135.515
no net on Bottom Solder "BOTTOMSOLDER1467" (solid, pour order 0): 44.7,136.785 44.7,137.485 46,137.485 46,136.785
no net on Bottom Solder "BOTTOMSOLDER1468" (solid, pour order 0): 44.7,138.055 44.7,138.755 46,138.755 46,138.055
no net on Bottom Solder "BOTTOMSOLDER1469" (solid, pour order 0): 21 vertices, not listed, extent 46.3,133.7 49.6,139.3
no net on Bottom Solder "BOTTOMSOLDER1470" (solid, pour order 0): 50.5,131.555 50.5,132.255 51.8,132.255 51.8,131.555
no net on Bottom Solder "BOTTOMSOLDER1471" (solid, pour order 0): 50.5,129.015 50.5,129.715 51.8,129.715 51.8,129.015
no net on Bottom Solder "BOTTOMSOLDER1472" (solid, pour order 0): 44.7,127.745 44.7,128.445 46,128.445 46,127.745
no net on Bottom Solder "BOTTOMSOLDER1473" (solid, pour order 0): 44.7,129.015 44.7,129.715 46,129.715 46,129.015
no net on Bottom Solder "BOTTOMSOLDER1474" (solid, pour order 0): 44.7,130.285 44.7,130.985 46,130.985 46,130.285
no net on Bottom Solder "BOTTOMSOLDER1475" (solid, pour order 0): 44.7,131.555 44.7,132.255 46,132.255 46,131.555
no net on Bottom Solder "BOTTOMSOLDER1476" (solid, pour order 0): 21 vertices, not listed, extent 46.3,127.2 49.6,132.8
no net on Bottom Solder "BOTTOMSOLDER1477" (solid, pour order 0): 177.055,124.45 177.055,125.75 177.755,125.75 177.755,124.45
no net on Bottom Solder "BOTTOMSOLDER1478" (solid, pour order 0): 174.515,124.45 174.515,125.75 175.215,125.75 175.215,124.45
no net on Bottom Solder "BOTTOMSOLDER1479" (solid, pour order 0): 173.245,130.25 173.245,131.55 173.945,131.55 173.945,130.25
no net on Bottom Solder "BOTTOMSOLDER1480" (solid, pour order 0): 174.515,130.25 174.515,131.55 175.215,131.55 175.215,130.25
no net on Bottom Solder "BOTTOMSOLDER1481" (solid, pour order 0): 175.785,130.25 175.785,131.55 176.485,131.55 176.485,130.25
no net on Bottom Solder "BOTTOMSOLDER1482" (solid, pour order 0): 177.055,130.25 177.055,131.55 177.755,131.55 177.755,130.25
no net on Bottom Solder "BOTTOMSOLDER1483" (solid, pour order 0): 21 vertices, not listed, extent 172.7,126.65 178.3,129.95
no net on Bottom Solder "BOTTOMSOLDER1484" (solid, pour order 0): 185.055,124.45 185.055,125.75 185.755,125.75 185.755,124.45
no net on Bottom Solder "BOTTOMSOLDER1485" (solid, pour order 0): 182.515,124.45 182.515,125.75 183.215,125.75 183.215,124.45
no net on Bottom Solder "BOTTOMSOLDER1486" (solid, pour order 0): 181.245,130.25 181.245,131.55 181.945,131.55 181.945,130.25
no net on Bottom Solder "BOTTOMSOLDER1487" (solid, pour order 0): 182.515,130.25 182.515,131.55 183.215,131.55 183.215,130.25
no net on Bottom Solder "BOTTOMSOLDER1488" (solid, pour order 0): 183.785,130.25 183.785,131.55 184.485,131.55 184.485,130.25
no net on Bottom Solder "BOTTOMSOLDER1489" (solid, pour order 0): 185.055,130.25 185.055,131.55 185.755,131.55 185.755,130.25
no net on Bottom Solder "BOTTOMSOLDER1490" (solid, pour order 0): 21 vertices, not listed, extent 180.7,126.65 186.3,129.95
no net on Bottom Solder "BOTTOMSOLDER1491" (solid, pour order 0): 193.055,124.45 193.055,125.75 193.755,125.75 193.755,124.45
no net on Bottom Solder "BOTTOMSOLDER1492" (solid, pour order 0): 190.515,124.45 190.515,125.75 191.215,125.75 191.215,124.45
no net on Bottom Solder "BOTTOMSOLDER1493" (solid, pour order 0): 189.245,130.25 189.245,131.55 189.945,131.55 189.945,130.25
no net on Bottom Solder "BOTTOMSOLDER1494" (solid, pour order 0): 190.515,130.25 190.515,131.55 191.215,131.55 191.215,130.25
no net on Bottom Solder "BOTTOMSOLDER1495" (solid, pour order 0): 191.785,130.25 191.785,131.55 192.485,131.55 192.485,130.25
no net on Bottom Solder "BOTTOMSOLDER1496" (solid, pour order 0): 193.055,130.25 193.055,131.55 193.755,131.55 193.755,130.25
no net on Bottom Solder "BOTTOMSOLDER1497" (solid, pour order 0): 21 vertices, not listed, extent 188.7,126.65 194.3,129.95
no net on Bottom Solder "BOTTOMSOLDER1498" (solid, pour order 0): 177.055,114.45 177.055,115.75 177.755,115.75 177.755,114.45
no net on Bottom Solder "BOTTOMSOLDER1499" (solid, pour order 0): 174.515,114.45 174.515,115.75 175.215,115.75 175.215,114.45
no net on Bottom Solder "BOTTOMSOLDER1500" (solid, pour order 0): 173.245,120.25 173.245,121.55 173.945,121.55 173.945,120.25
no net on Bottom Solder "BOTTOMSOLDER1501" (solid, pour order 0): 174.515,120.25 174.515,121.55 175.215,121.55 175.215,120.25
no net on Bottom Solder "BOTTOMSOLDER1502" (solid, pour order 0): 175.785,120.25 175.785,121.55 176.485,121.55 176.485,120.25
no net on Bottom Solder "BOTTOMSOLDER1503" (solid, pour order 0): 177.055,120.25 177.055,121.55 177.755,121.55 177.755,120.25
no net on Bottom Solder "BOTTOMSOLDER1504" (solid, pour order 0): 21 vertices, not listed, extent 172.7,116.65 178.3,119.95
no net on Bottom Solder "BOTTOMSOLDER1505" (solid, pour order 0): 185.055,114.45 185.055,115.75 185.755,115.75 185.755,114.45
no net on Bottom Solder "BOTTOMSOLDER1506" (solid, pour order 0): 182.515,114.45 182.515,115.75 183.215,115.75 183.215,114.45
no net on Bottom Solder "BOTTOMSOLDER1507" (solid, pour order 0): 181.245,120.25 181.245,121.55 181.945,121.55 181.945,120.25
no net on Bottom Solder "BOTTOMSOLDER1508" (solid, pour order 0): 182.515,120.25 182.515,121.55 183.215,121.55 183.215,120.25
no net on Bottom Solder "BOTTOMSOLDER1509" (solid, pour order 0): 183.785,120.25 183.785,121.55 184.485,121.55 184.485,120.25
no net on Bottom Solder "BOTTOMSOLDER1510" (solid, pour order 0): 185.055,120.25 185.055,121.55 185.755,121.55 185.755,120.25
no net on Bottom Solder "BOTTOMSOLDER1511" (solid, pour order 0): 21 vertices, not listed, extent 180.7,116.65 186.3,119.95
no net on Bottom Solder "BOTTOMSOLDER1512" (solid, pour order 0): 193.055,114.45 193.055,115.75 193.755,115.75 193.755,114.45
no net on Bottom Solder "BOTTOMSOLDER1513" (solid, pour order 0): 190.515,114.45 190.515,115.75 191.215,115.75 191.215,114.45
no net on Bottom Solder "BOTTOMSOLDER1514" (solid, pour order 0): 189.245,120.25 189.245,121.55 189.945,121.55 189.945,120.25
no net on Bottom Solder "BOTTOMSOLDER1515" (solid, pour order 0): 190.515,120.25 190.515,121.55 191.215,121.55 191.215,120.25
no net on Bottom Solder "BOTTOMSOLDER1516" (solid, pour order 0): 191.785,120.25 191.785,121.55 192.485,121.55 192.485,120.25
no net on Bottom Solder "BOTTOMSOLDER1517" (solid, pour order 0): 193.055,120.25 193.055,121.55 193.755,121.55 193.755,120.25
no net on Bottom Solder "BOTTOMSOLDER1518" (solid, pour order 0): 21 vertices, not listed, extent 188.7,116.65 194.3,119.95
no net on Bottom Solder "BOTTOMSOLDER1519" (solid, pour order 0): 50.5,78.055 50.5,78.755 51.8,78.755 51.8,78.055
no net on Bottom Solder "BOTTOMSOLDER1520" (solid, pour order 0): 50.5,75.515 50.5,76.215 51.8,76.215 51.8,75.515
no net on Bottom Solder "BOTTOMSOLDER1521" (solid, pour order 0): 44.7,74.245 44.7,74.945 46,74.945 46,74.245
no net on Bottom Solder "BOTTOMSOLDER1522" (solid, pour order 0): 44.7,75.515 44.7,76.215 46,76.215 46,75.515
no net on Bottom Solder "BOTTOMSOLDER1523" (solid, pour order 0): 44.7,76.785 44.7,77.485 46,77.485 46,76.785
no net on Bottom Solder "BOTTOMSOLDER1524" (solid, pour order 0): 44.7,78.055 44.7,78.755 46,78.755 46,78.055
no net on Bottom Solder "BOTTOMSOLDER1525" (solid, pour order 0): 21 vertices, not listed, extent 46.3,73.7 49.6,79.3
no net on Bottom Solder "BOTTOMSOLDER1526" (solid, pour order 0): 50.5,71.555 50.5,72.255 51.8,72.255 51.8,71.555
no net on Bottom Solder "BOTTOMSOLDER1527" (solid, pour order 0): 50.5,69.015 50.5,69.715 51.8,69.715 51.8,69.015
no net on Bottom Solder "BOTTOMSOLDER1528" (solid, pour order 0): 44.7,67.745 44.7,68.445 46,68.445 46,67.745
no net on Bottom Solder "BOTTOMSOLDER1529" (solid, pour order 0): 44.7,69.015 44.7,69.715 46,69.715 46,69.015
no net on Bottom Solder "BOTTOMSOLDER1530" (solid, pour order 0): 44.7,70.285 44.7,70.985 46,70.985 46,70.285
no net on Bottom Solder "BOTTOMSOLDER1531" (solid, pour order 0): 44.7,71.555 44.7,72.255 46,72.255 46,71.555
no net on Bottom Solder "BOTTOMSOLDER1532" (solid, pour order 0): 21 vertices, not listed, extent 46.3,67.2 49.6,72.8
no net on Bottom Solder "BOTTOMSOLDER1533" (solid, pour order 0): 177.055,64.45 177.055,65.75 177.755,65.75 177.755,64.45
no net on Bottom Solder "BOTTOMSOLDER1534" (solid, pour order 0): 174.515,64.45 174.515,65.75 175.215,65.75 175.215,64.45
no net on Bottom Solder "BOTTOMSOLDER1535" (solid, pour order 0): 173.245,70.25 173.245,71.55 173.945,71.55 173.945,70.25
no net on Bottom Solder "BOTTOMSOLDER1536" (solid, pour order 0): 174.515,70.25 174.515,71.55 175.215,71.55 175.215,70.25
no net on Bottom Solder "BOTTOMSOLDER1537" (solid, pour order 0): 175.785,70.25 175.785,71.55 176.485,71.55 176.485,70.25
no net on Bottom Solder "BOTTOMSOLDER1538" (solid, pour order 0): 177.055,70.25 177.055,71.55 177.755,71.55 177.755,70.25
no net on Bottom Solder "BOTTOMSOLDER1539" (solid, pour order 0): 21 vertices, not listed, extent 172.7,66.65 178.3,69.95
no net on Bottom Solder "BOTTOMSOLDER1540" (solid, pour order 0): 185.055,64.45 185.055,65.75 185.755,65.75 185.755,64.45
no net on Bottom Solder "BOTTOMSOLDER1541" (solid, pour order 0): 182.515,64.45 182.515,65.75 183.215,65.75 183.215,64.45
no net on Bottom Solder "BOTTOMSOLDER1542" (solid, pour order 0): 181.245,70.25 181.245,71.55 181.945,71.55 181.945,70.25
no net on Bottom Solder "BOTTOMSOLDER1543" (solid, pour order 0): 182.515,70.25 182.515,71.55 183.215,71.55 183.215,70.25
no net on Bottom Solder "BOTTOMSOLDER1544" (solid, pour order 0): 183.785,70.25 183.785,71.55 184.485,71.55 184.485,70.25
no net on Bottom Solder "BOTTOMSOLDER1545" (solid, pour order 0): 185.055,70.25 185.055,71.55 185.755,71.55 185.755,70.25
no net on Bottom Solder "BOTTOMSOLDER1546" (solid, pour order 0): 21 vertices, not listed, extent 180.7,66.65 186.3,69.95
no net on Bottom Solder "BOTTOMSOLDER1547" (solid, pour order 0): 193.055,64.45 193.055,65.75 193.755,65.75 193.755,64.45
no net on Bottom Solder "BOTTOMSOLDER1548" (solid, pour order 0): 190.515,64.45 190.515,65.75 191.215,65.75 191.215,64.45
no net on Bottom Solder "BOTTOMSOLDER1549" (solid, pour order 0): 189.245,70.25 189.245,71.55 189.945,71.55 189.945,70.25
no net on Bottom Solder "BOTTOMSOLDER1550" (solid, pour order 0): 190.515,70.25 190.515,71.55 191.215,71.55 191.215,70.25
no net on Bottom Solder "BOTTOMSOLDER1551" (solid, pour order 0): 191.785,70.25 191.785,71.55 192.485,71.55 192.485,70.25
no net on Bottom Solder "BOTTOMSOLDER1552" (solid, pour order 0): 193.055,70.25 193.055,71.55 193.755,71.55 193.755,70.25
no net on Bottom Solder "BOTTOMSOLDER1553" (solid, pour order 0): 21 vertices, not listed, extent 188.7,66.65 194.3,69.95
no net on Bottom Solder "BOTTOMSOLDER1554" (solid, pour order 0): 177.055,54.45 177.055,55.75 177.755,55.75 177.755,54.45
no net on Bottom Solder "BOTTOMSOLDER1555" (solid, pour order 0): 174.515,54.45 174.515,55.75 175.215,55.75 175.215,54.45
no net on Bottom Solder "BOTTOMSOLDER1556" (solid, pour order 0): 173.245,60.25 173.245,61.55 173.945,61.55 173.945,60.25
no net on Bottom Solder "BOTTOMSOLDER1557" (solid, pour order 0): 174.515,60.25 174.515,61.55 175.215,61.55 175.215,60.25
no net on Bottom Solder "BOTTOMSOLDER1558" (solid, pour order 0): 175.785,60.25 175.785,61.55 176.485,61.55 176.485,60.25
no net on Bottom Solder "BOTTOMSOLDER1559" (solid, pour order 0): 177.055,60.25 177.055,61.55 177.755,61.55 177.755,60.25
no net on Bottom Solder "BOTTOMSOLDER1560" (solid, pour order 0): 21 vertices, not listed, extent 172.7,56.65 178.3,59.95
no net on Bottom Solder "BOTTOMSOLDER1561" (solid, pour order 0): 185.055,54.45 185.055,55.75 185.755,55.75 185.755,54.45
no net on Bottom Solder "BOTTOMSOLDER1562" (solid, pour order 0): 182.515,54.45 182.515,55.75 183.215,55.75 183.215,54.45
no net on Bottom Solder "BOTTOMSOLDER1563" (solid, pour order 0): 181.245,60.25 181.245,61.55 181.945,61.55 181.945,60.25
no net on Bottom Solder "BOTTOMSOLDER1564" (solid, pour order 0): 182.515,60.25 182.515,61.55 183.215,61.55 183.215,60.25
no net on Bottom Solder "BOTTOMSOLDER1565" (solid, pour order 0): 183.785,60.25 183.785,61.55 184.485,61.55 184.485,60.25
no net on Bottom Solder "BOTTOMSOLDER1566" (solid, pour order 0): 185.055,60.25 185.055,61.55 185.755,61.55 185.755,60.25
no net on Bottom Solder "BOTTOMSOLDER1567" (solid, pour order 0): 21 vertices, not listed, extent 180.7,56.65 186.3,59.95
no net on Bottom Solder "BOTTOMSOLDER1568" (solid, pour order 0): 193.055,54.45 193.055,55.75 193.755,55.75 193.755,54.45
no net on Bottom Solder "BOTTOMSOLDER1569" (solid, pour order 0): 190.515,54.45 190.515,55.75 191.215,55.75 191.215,54.45
no net on Bottom Solder "BOTTOMSOLDER1570" (solid, pour order 0): 189.245,60.25 189.245,61.55 189.945,61.55 189.945,60.25
no net on Bottom Solder "BOTTOMSOLDER1571" (solid, pour order 0): 190.515,60.25 190.515,61.55 191.215,61.55 191.215,60.25
no net on Bottom Solder "BOTTOMSOLDER1572" (solid, pour order 0): 191.785,60.25 191.785,61.55 192.485,61.55 192.485,60.25
no net on Bottom Solder "BOTTOMSOLDER1573" (solid, pour order 0): 193.055,60.25 193.055,61.55 193.755,61.55 193.755,60.25
no net on Bottom Solder "BOTTOMSOLDER1574" (solid, pour order 0): 21 vertices, not listed, extent 188.7,56.65 194.3,59.95
no net on Bottom Solder "BOTTOMSOLDER1575" (solid, pour order 0): 50.5,258.055 50.5,258.755 51.8,258.755 51.8,258.055
no net on Bottom Solder "BOTTOMSOLDER1576" (solid, pour order 0): 50.5,255.515 50.5,256.215 51.8,256.215 51.8,255.515
no net on Bottom Solder "BOTTOMSOLDER1577" (solid, pour order 0): 44.7,254.245 44.7,254.945 46,254.945 46,254.245
no net on Bottom Solder "BOTTOMSOLDER1578" (solid, pour order 0): 44.7,255.515 44.7,256.215 46,256.215 46,255.515
no net on Bottom Solder "BOTTOMSOLDER1579" (solid, pour order 0): 44.7,256.785 44.7,257.485 46,257.485 46,256.785
no net on Bottom Solder "BOTTOMSOLDER1580" (solid, pour order 0): 44.7,258.055 44.7,258.755 46,258.755 46,258.055
no net on Bottom Solder "BOTTOMSOLDER1581" (solid, pour order 0): 21 vertices, not listed, extent 46.3,253.7 49.6,259.3
no net on Bottom Solder "BOTTOMSOLDER1582" (solid, pour order 0): 50.5,251.555 50.5,252.255 51.8,252.255 51.8,251.555
no net on Bottom Solder "BOTTOMSOLDER1583" (solid, pour order 0): 50.5,249.015 50.5,249.715 51.8,249.715 51.8,249.015
no net on Bottom Solder "BOTTOMSOLDER1584" (solid, pour order 0): 44.7,247.745 44.7,248.445 46,248.445 46,247.745
no net on Bottom Solder "BOTTOMSOLDER1585" (solid, pour order 0): 44.7,249.015 44.7,249.715 46,249.715 46,249.015
no net on Bottom Solder "BOTTOMSOLDER1586" (solid, pour order 0): 44.7,250.285 44.7,250.985 46,250.985 46,250.285
no net on Bottom Solder "BOTTOMSOLDER1587" (solid, pour order 0): 44.7,251.555 44.7,252.255 46,252.255 46,251.555
no net on Bottom Solder "BOTTOMSOLDER1588" (solid, pour order 0): 21 vertices, not listed, extent 46.3,247.2 49.6,252.8
no net on Bottom Solder "BOTTOMSOLDER1589" (solid, pour order 0): 50.5,198.055 50.5,198.755 51.8,198.755 51.8,198.055
no net on Bottom Solder "BOTTOMSOLDER1590" (solid, pour order 0): 50.5,195.515 50.5,196.215 51.8,196.215 51.8,195.515
no net on Bottom Solder "BOTTOMSOLDER1591" (solid, pour order 0): 44.7,194.245 44.7,194.945 46,194.945 46,194.245
no net on Bottom Solder "BOTTOMSOLDER1592" (solid, pour order 0): 44.7,195.515 44.7,196.215 46,196.215 46,195.515
no net on Bottom Solder "BOTTOMSOLDER1593" (solid, pour order 0): 44.7,196.785 44.7,197.485 46,197.485 46,196.785
no net on Bottom Solder "BOTTOMSOLDER1594" (solid, pour order 0): 44.7,198.055 44.7,198.755 46,198.755 46,198.055
no net on Bottom Solder "BOTTOMSOLDER1595" (solid, pour order 0): 21 vertices, not listed, extent 46.3,193.7 49.6,199.3
no net on Bottom Solder "BOTTOMSOLDER1596" (solid, pour order 0): 50.5,191.555 50.5,192.255 51.8,192.255 51.8,191.555
no net on Bottom Solder "BOTTOMSOLDER1597" (solid, pour order 0): 50.5,189.015 50.5,189.715 51.8,189.715 51.8,189.015
no net on Bottom Solder "BOTTOMSOLDER1598" (solid, pour order 0): 44.7,187.745 44.7,188.445 46,188.445 46,187.745
no net on Bottom Solder "BOTTOMSOLDER1599" (solid, pour order 0): 44.7,189.015 44.7,189.715 46,189.715 46,189.015
no net on Bottom Solder "BOTTOMSOLDER1600" (solid, pour order 0): 44.7,190.285 44.7,190.985 46,190.985 46,190.285
no net on Bottom Solder "BOTTOMSOLDER1601" (solid, pour order 0): 44.7,191.555 44.7,192.255 46,192.255 46,191.555
no net on Bottom Solder "BOTTOMSOLDER1602" (solid, pour order 0): 21 vertices, not listed, extent 46.3,187.2 49.6,192.8
no net on Bottom Solder "BOTTOMSOLDER1603" (solid, pour order 0): 177.055,184.45 177.055,185.75 177.755,185.75 177.755,184.45
no net on Bottom Solder "BOTTOMSOLDER1604" (solid, pour order 0): 174.515,184.45 174.515,185.75 175.215,185.75 175.215,184.45
no net on Bottom Solder "BOTTOMSOLDER1605" (solid, pour order 0): 173.245,190.25 173.245,191.55 173.945,191.55 173.945,190.25
no net on Bottom Solder "BOTTOMSOLDER1606" (solid, pour order 0): 174.515,190.25 174.515,191.55 175.215,191.55 175.215,190.25
no net on Bottom Solder "BOTTOMSOLDER1607" (solid, pour order 0): 175.785,190.25 175.785,191.55 176.485,191.55 176.485,190.25
no net on Bottom Solder "BOTTOMSOLDER1608" (solid, pour order 0): 177.055,190.25 177.055,191.55 177.755,191.55 177.755,190.25
no net on Bottom Solder "BOTTOMSOLDER1609" (solid, pour order 0): 21 vertices, not listed, extent 172.7,186.65 178.3,189.95
no net on Bottom Solder "BOTTOMSOLDER1610" (solid, pour order 0): 185.055,184.45 185.055,185.75 185.755,185.75 185.755,184.45
no net on Bottom Solder "BOTTOMSOLDER1611" (solid, pour order 0): 182.515,184.45 182.515,185.75 183.215,185.75 183.215,184.45
no net on Bottom Solder "BOTTOMSOLDER1612" (solid, pour order 0): 181.245,190.25 181.245,191.55 181.945,191.55 181.945,190.25
no net on Bottom Solder "BOTTOMSOLDER1613" (solid, pour order 0): 182.515,190.25 182.515,191.55 183.215,191.55 183.215,190.25
no net on Bottom Solder "BOTTOMSOLDER1614" (solid, pour order 0): 183.785,190.25 183.785,191.55 184.485,191.55 184.485,190.25
no net on Bottom Solder "BOTTOMSOLDER1615" (solid, pour order 0): 185.055,190.25 185.055,191.55 185.755,191.55 185.755,190.25
no net on Bottom Solder "BOTTOMSOLDER1616" (solid, pour order 0): 21 vertices, not listed, extent 180.7,186.65 186.3,189.95
no net on Bottom Solder "BOTTOMSOLDER1617" (solid, pour order 0): 193.055,184.45 193.055,185.75 193.755,185.75 193.755,184.45
no net on Bottom Solder "BOTTOMSOLDER1618" (solid, pour order 0): 190.515,184.45 190.515,185.75 191.215,185.75 191.215,184.45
